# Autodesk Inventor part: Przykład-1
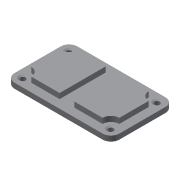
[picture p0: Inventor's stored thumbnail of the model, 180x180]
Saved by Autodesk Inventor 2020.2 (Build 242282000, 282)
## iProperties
Created: 2006-03
Part Number: Przykład-1
Document SubType Name: Modeling
Designer: F.Stasiak
Density: 1 g/cm^3
Material: Ogólny
Appearance: Domyślna
Manager: www.cadconsulting.pl
Company: Fabian Stasiak CAD Consulting
Author: F.Stasiak
Subject: Zbiór ćwiczeń. Autodesk Inventor 2020. Kurs podstawowy
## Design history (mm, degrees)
sketch "Szkic1"
  geometry: L1 (-42, 30)-(42, 30); L2 (50, 22)-(50, -22); L3 (42, -30)-(-42, -30); L4 (-50, -22)-(-50, 22); L5 (0, 30)-(0, -30); A1 r 8 centre (42, 22) between (50, 22) and (42, 30); A2 r 8 centre (42, -22) between (42, -30) and (50, -22); A3 r 8 centre (-42, -22) between (-50, -22) and (-42, -30); A4 r 8 centre (-42, 22) between (-42, 30) and (-50, 22); 2 further points
  constraints: 10 end point, 8 point on circle, 8 tangent, 4 centre point, 3 equal radius, 3 midpoint, 2 parallel, 1 coincident, 1 horizontal, 1 perpendicular
  dimensions: "d2" = 100 distance between parallel lines of L2 L4; "d3" = 60 distance between parallel lines of L1 L3; "d19" = 8 radius of A1
extrude "Wyciągnięcie proste1" new body sketch "Szkic1" distance "d4" = 5; taper "d5" = 0 deg
sketch "Szkic2"
  geometry: L1 (-42, 30)-(42, 30) reference; L2 (-50, -22)-(-50, 22) reference; L3 (42, -30)-(-42, -30) reference; L4 (50, 22)-(50, -22) reference; A1 r 8 centre (42, 22) between (50, 22) and (42, 30) reference; A2 r 8 centre (-42, 22) between (-42, 30) and (-50, 22) reference; A3 r 8 centre (-42, -22) between (-50, -22) and (-42, -30) reference; A4 r 8 centre (42, -22) between (42, -30) and (50, -22) reference
hole "Otwór1" sketch "Szkic2" at (-42, 22), (42, 22), (42, -22), (-42, -22) diameter "d6" = 5; stored, may be unused: countersink angle "d10" = 120 deg, drill point angle "d12" = 118 deg; dims "d7" = 6, "d8" = 8, "d9" = 2, "d11" = 8
sketch "Szkic3"
  geometry: L1 (-42, 14)-(-42, -14); L2 (-34, 22)-(-7, 22); L3 (-7, 22)-(-7, -22); L4 (-7, -22)-(-34, -22); L5 (-42, 14)-(-42, 22); L6 (-34, 22)-(-42, 22); L7 (-42, -21.218)-(-42, -14); L8 (-42, -22)-(-34, -22); C1 r 2.5 at (-42, 22) reference; C2 r 2.5 at (-42, -22) reference; A1 r 8 centre (-42, 22) between (-42, 30) and (-50, 22) reference; A2 r 8 centre (-42, -22) between (-50, -22) and (-42, -30) reference; A3 r 8 centre (-42, 22) between (-34, 22) and (-42, 14); A4 r 8 centre (-42, -22) between (-42, -14) and (-34, -22); 1 other entity
  constraints: 16 end point, 5 perpendicular, 4 point on circle, 2 centre point, 2 coincident, 2 concentric, 1 horizontal, 1 parallel, 1 vertical, 3 other
  dimensions: "d17" = 35 distance between parallel lines of L3 L1
extrude "Wyciągnięcie proste2" join sketch "Szkic3" distance "d14" = 5; taper "d15" = 0 deg
mirror "Lustro1"
node "Bryła1"
node "Korpusy bryłowe"
node "Korpusy powierzchniowe"
node "Pętla rzutowana1"
